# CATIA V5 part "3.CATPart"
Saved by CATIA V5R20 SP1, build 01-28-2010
Part number: 3
Publications: "L", "Droite.1", "Droite.2", "Plan.1"
Bounding box of the stored display mesh (mm): x 0 to 0, y 20 to 20, z 109.283 to 129.283
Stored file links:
  C:\Users\Geoffray\Documents\Ifma\IAO\Exercice IAO\Catia\3.CATPart
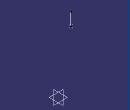
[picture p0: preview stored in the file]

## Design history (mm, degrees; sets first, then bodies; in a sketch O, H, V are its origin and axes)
Body1 (main body)
  Point1 "L": stored without definition
  Point2 "L": (0, 0, 0), relative to Point1
  Line1: type PtDir, RefPoint Point2, Direction yz-plane, Start -20, End 20
  Line2: stored without definition
  Line3: type PtDir, RefPoint Point2, Direction Line2, Start 0, End 20
  Plane1: type Offset, RefPlane yz-plane, Offset 0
